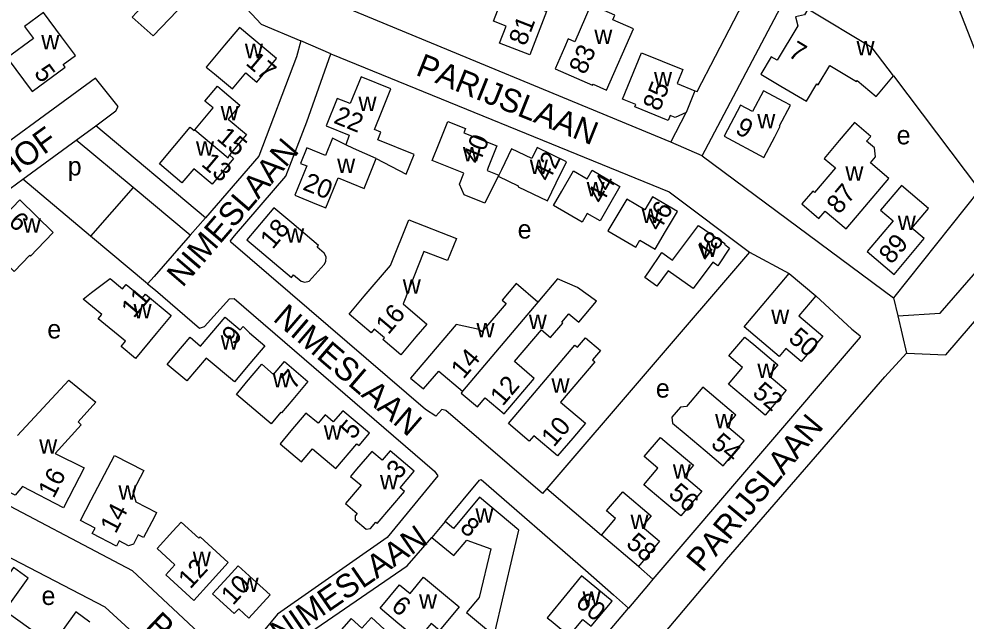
# Model space of a CAD drawing. Extents: x 157768 to 159790, y 387230 to 389604.
# Drawn here: x 158292.2 to 158494.9, y 388797.9 to 388926.9 of the extents above; entities that cross this region are included whole.
import ezdxf

# ---------------------------------------------------------------- set-up
doc = ezdxf.new("R2010")
doc.units = 0
for name, color, linetype in [('BLT_Basislijn', 7, 'Continuous'), ('BLT_Bebouwing', 7, 'Continuous'), ('BLT_Centroide', 7, 'Continuous'), ('BLT_Huisnummer', 7, 'Continuous'), ('BLT_Onderverdeling_panden', 7, 'Continuous'), ('BLT_Straatnaam', 7, 'Continuous')]:
    doc.layers.add(name, color=color, linetype=linetype)

msp = doc.modelspace()

# ---------------------------------------------------------------- linework, layer by layer
at = {"layer": 'BLT_Basislijn'}
for p, q in [((158431.74, 388900.51), (158362.74, 388929.08)), ((158358.97, 388919.46), (158352.55, 388922.18)), ((158304.47, 388900.97), (158308.62, 388904.02)), ((158332.14, 388884.34), (158308.62, 388904.02)), ((158293.03, 388892.57), (158304.47, 388900.97)), ((158316.62, 388890.8), (158304.47, 388900.97)), ((158438.43, 388897.56), (158431.74, 388900.51)), ((158255.34, 388864.91), (158293.03, 388892.57)), ((158307.51, 388880.4), (158293.03, 388892.57)), ((158316.62, 388890.8), (158307.51, 388880.4)), ((158328.86, 388880.57), (158316.62, 388890.8)), ((158332.14, 388884.34), (158328.86, 388880.57)), ((158319.7, 388870.15), (158307.51, 388880.4)), ((158448.59, 388876.93), (158405.18, 388826.37)), ((158448.59, 388876.93), (158457.1, 388872.4)), ((158480.33, 388863.3), (158482.23, 388855.29)), ((158383.44, 388819.3), (158390.75, 388828.15)), ((158390.75, 388828.15), (158391.16, 388828.23)), ((158391.16, 388828.23), (158413.5, 388808.81)), ((158405.18, 388826.37), (158416.89, 388816.34)), ((158375.33, 388809.8), (158380.57, 388815.86)), ((158352.11, 388793.82), (158375.33, 388809.8)), ((158427.9, 388806.93), (158424.82, 388809.65)), ((158413.5, 388808.81), (158419.44, 388803.53)), ((158419.44, 388803.53), (158422.65, 388800.7)), ((158416.4, 388793.31), (158422.65, 388800.7))]:
    msp.add_line(p, q, dxfattribs=at)
for points in [[(158217.7, 388922.2), (158241.39, 388936.76), (158256.85, 388946.34), (158278.36, 388958.55), (158301, 388970.67), (158302.4, 388970.48), (158344.06, 388925.81), (158352.55, 388922.18)], [(158505.09, 388881.94), (158513.06, 388891.11), (158498.54, 388915.97), (158492.75, 388930.78), (158491.71, 388938.14)], [(158436.91, 388911.53), (158437.35, 388911.35), (158449.16, 388934.14)], [(158438.43, 388897.56), (158456.57, 388931.96)], [(158352.55, 388922.18), (158351.59, 388918.78), (158343.57, 388897.49), (158332.14, 388884.34)], [(158405.18, 388826.37), (158404.25, 388825.3), (158383.56, 388843.02), (158382.69, 388843.23), (158381.47, 388841.81), (158379.24, 388843.24), (158337.52, 388879.07), (158337.46, 388879.39), (158338.33, 388880.47), (158349.31, 388893.24), (158353.79, 388904.84), (158358.97, 388919.46)], [(158358.97, 388919.46), (158431.36, 388889.84), (158448.59, 388876.93)], [(158308.62, 388904.02), (158312.94, 388907.19), (158313.42, 388908.14), (158308.58, 388914.19), (158250.43, 388871.67)], [(158479.43, 388914.71), (158497.83, 388890.31), (158479.42, 388867.16)], [(158431.74, 388900.51), (158435.02, 388906.85)], [(158438.43, 388897.56), (158479.42, 388867.16)], [(158482.23, 388855.29), (158490.58, 388854.93), (158513.94, 388882.12), (158517.63, 388885.18), (158521.9, 388885.49), (158565.66, 388865.34), (158569.12, 388863.56), (158573.32, 388860.89)], [(158328.86, 388880.57), (158321.16, 388871.71), (158319.7, 388870.15)], [(158480.33, 388863.3), (158489.42, 388863.92), (158505.09, 388881.94)], [(158319.7, 388870.15), (158321.4, 388868.83), (158330.85, 388860.65), (158331.93, 388861), (158337.3, 388866.95), (158338.24, 388867.06), (158381.15, 388830.03), (158381.88, 388829.07), (158371.05, 388815.86), (158347.55, 388799.4), (158338.32, 388788.26)], [(158462.77, 388867.62), (158470.5, 388860.47), (158472.2, 388859.12), (158472.25, 388858.78), (158427.9, 388806.93)], [(158479.42, 388867.16), (158480.33, 388863.3)], [(158255.34, 388864.91), (158283.64, 388826.08), (158316.42, 388808.74), (158338.32, 388788.26)], [(158435.57, 388745.97), (158422.92, 388761.25), (158425, 388788.91), (158431.41, 388796.6), (158443.67, 388811.14), (158477.57, 388850.28), (158482.23, 388855.29)], [(158345.09, 388769.27), (158310.62, 388800.89), (158285.46, 388813.98), (158277.79, 388808.18)], [(158427.9, 388806.93), (158426.93, 388805.79), (158422.65, 388800.7)]]:
    msp.add_lwpolyline(points, dxfattribs=at)
at = {"layer": 'BLT_Bebouwing'}
for p, q in [((158457.1, 388872.4), (158462.77, 388867.62)), ((158424.82, 388809.65), (158416.89, 388816.34))]:
    msp.add_line(p, q, dxfattribs=at)
for points in [[(158325.04, 388930.87), (158328.72, 388934.25), (158322.66, 388940.88), (158319.8, 388938.27), (158318.62, 388939.56), (158318.96, 388939.86), (158315.64, 388943.49), (158311.96, 388940.11), (158310.44, 388938.72), (158314.96, 388933.78), (158314.52, 388933.38), (158318.3, 388929.25), (158316.42, 388927.26), (158320.96, 388923.28), (158326.06, 388928.65), (158324.3, 388930.2), (158325.04, 388930.87)], [(158403.34, 388923.89), (158401.53, 388919.23), (158395.1, 388921.73), (158396.51, 388925.38), (158393.79, 388926.42), (158396.17, 388932.56), (158397.31, 388935.48), (158402.89, 388933.31), (158401.57, 388929.91), (158405.14, 388928.52), (158403.34, 388923.89)], [(158415.16, 388929.68), (158414.63, 388929.91), (158411.18, 388921.99), (158409.77, 388922.61), (158408.97, 388920.78), (158406.97, 388916.2), (158415, 388912.7), (158415.09, 388912.9), (158418, 388911.63), (158423.74, 388924.79), (158419.32, 388926.72), (158419.74, 388927.68), (158415.16, 388929.68)], [(158301.3, 388923.07), (158297.44, 388928.29), (158293.4, 388925.3), (158295.32, 388922.71), (158289.69, 388918.55), (158295.02, 388911.34), (158302.06, 388916.54), (158301.64, 388917.11), (158304.27, 388919.05), (158301.3, 388923.07)], [(158461.07, 388928.97), (158460.36, 388927.8), (158458.42, 388927.34), (158458.94, 388925.45), (158454.49, 388918.05), (158453.25, 388918.79), (158451.04, 388915.11), (158455.32, 388912.53), (158460.76, 388909.26), (158463, 388912.98), (158463.31, 388912.8), (158465.81, 388916.96), (158471.5, 388913.53), (158471.64, 388913.7), (158475.72, 388910.27), (158476.23, 388910.88), (158479.43, 388914.71)], [(158479.43, 388914.71), (158474.87, 388920.68), (158461.07, 388928.97)], [(158336.17, 388921.26), (158332.3, 388916.6), (158334.05, 388915.14), (158337.88, 388911.93), (158340.75, 388915.35), (158343.11, 388913.36), (158347.35, 388918.4), (158339.39, 388925.09), (158336.17, 388921.26)], [(158435.02, 388906.85), (158432.66, 388905.81), (158431.61, 388906.23), (158431.19, 388905.18), (158424.01, 388908.08), (158424.23, 388908.61), (158421.43, 388909.74), (158425.43, 388919.66)], [(158425.43, 388919.66), (158434.28, 388916.09), (158433.07, 388913.07), (158436.91, 388911.53)], [(158369.93, 388907.31), (158371.81, 388911.94), (158365.44, 388914.52), (158363.1, 388908.76), (158360.32, 388909.89), (158357.93, 388903.99), (158362.9, 388901.98), (158362.17, 388899.97)], [(158329.82, 388903.14), (158333.76, 388907.84), (158332, 388909.32), (158334.68, 388912.51), (158335.68, 388911.67), (158339.51, 388908.45), (158336.98, 388905.44), (158340.91, 388902.13), (158337.24, 388897.77)], [(158436.91, 388911.53), (158435.02, 388906.85)], [(158456.01, 388909.14), (158451.59, 388911.48), (158449.24, 388907.05), (158446.67, 388908.41), (158443.14, 388901.77), (158451.65, 388897.26), (158453.99, 388901.68), (158455.18, 388903.92), (158455.01, 388904.01), (158457.35, 388908.43), (158456.01, 388909.14)], [(158368.65, 388896.99), (158375.11, 388893.65), (158376.82, 388897.86), (158369.02, 388901.02), (158369.69, 388902.66), (158368.28, 388903.23), (158369.93, 388907.31)], [(158394.8, 388893.22), (158391.9, 388887.45), (158387.53, 388889.2), (158386.5, 388891.53), (158387.45, 388893.89), (158380.68, 388896.61), (158382.16, 388900.31), (158384.02, 388904.95), (158387.81, 388903.43), (158387.45, 388902.54), (158394.51, 388899.71), (158392.65, 388895.07)], [(158337.24, 388897.77), (158338.14, 388897.01), (158333.54, 388891.53), (158329.62, 388894.83), (158327.09, 388891.83), (158322.28, 388895.89), (158328.84, 388903.69), (158329.68, 388902.98), (158329.82, 388903.14)], [(158472.51, 388885.74), (158478.42, 388892.74), (158474.48, 388896.06), (158475.57, 388897.36), (158475.36, 388899.27), (158473.65, 388900.71), (158474.54, 388901.76), (158471.04, 388904.71), (158467.79, 388900.86), (158464.57, 388897.04), (158466.97, 388895.01), (158462.51, 388889.72), (158462.14, 388890.03), (158459.81, 388887.27), (158463.45, 388884.19), (158464.75, 388885.74), (158469.28, 388881.92), (158472.51, 388885.74)], [(158362.17, 388899.97), (158359.34, 388901.38), (158357.85, 388897.69), (158353.8, 388899.33), (158352.44, 388895.97), (158353.82, 388895.41), (158351.27, 388889.14), (158355.91, 388887.26), (158357.91, 388886.44), (158360.52, 388892.86), (158366.06, 388890.61), (158368.65, 388896.99)], [(158407.23, 388891.83), (158409.42, 388896.32), (158403.15, 388899.38), (158401.98, 388896.99), (158397.67, 388899.09), (158395.47, 388894.6), (158394.91, 388893.45)], [(158392.65, 388895.07), (158392.4, 388894.46), (158394.91, 388893.45)], [(158394.8, 388893.22), (158399.04, 388891.16), (158399.05, 388890.97), (158405.32, 388887.92), (158407.23, 388891.83)], [(158418.36, 388886.69), (158416.59, 388883.63), (158413.83, 388885.23), (158412.75, 388883.37), (158406.62, 388886.92), (158408.41, 388890.02), (158410.92, 388894.34), (158413.82, 388892.66), (158414.88, 388894.48), (158420.86, 388891.01), (158418.36, 388886.69)], [(158481.11, 388891.2), (158476.66, 388885.93), (158479.32, 388883.68), (158473.75, 388877.09), (158479.53, 388872.19), (158486.01, 388879.85), (158483.36, 388882.09), (158486.91, 388886.29), (158481.11, 388891.2)], [(158430.59, 388881.36), (158433.15, 388885.65), (158427.83, 388888.83), (158426.15, 388886.01), (158422.32, 388888.29), (158419.75, 388884), (158418.29, 388881.55), (158424.22, 388878.01), (158425.14, 388879.55), (158428.36, 388877.62), (158430.59, 388881.36)], [(158296.06, 388877.57), (158299.55, 388881.15), (158292.39, 388888.13), (158287.49, 388883.11), (158289.87, 388880.79), (158286.52, 388877.35), (158290.1, 388873.86), (158291.15, 388872.83), (158294.51, 388876.28), (158294.66, 388876.13), (158296.06, 388877.57)], [(158357.51, 388876.77), (158356, 388878.05), (158356.29, 388878.38), (158350.58, 388883.21), (158346.77, 388886.44), (158340.95, 388879.57), (158350.51, 388871.55), (158350.99, 388872.12), (158352.58, 388870.77), (158353.41, 388870.52), (158354.31, 388870.76), (158357.54, 388874.34), (158357.9, 388874.98), (158357.93, 388875.92), (158357.51, 388876.77)], [(158377.19, 388858.81), (158373.96, 388854.99), (158370.12, 388858.24), (158370.43, 388858.61), (158368.27, 388860.44), (158367.62, 388859.67), (158362.88, 388863.69), (158366.11, 388867.5), (158371.72, 388874.13), (158375.69, 388883.91), (158385.85, 388879.85), (158383.96, 388875.16), (158378.89, 388877.1), (158374.44, 388865.86), (158379.52, 388861.55), (158377.19, 388858.81)], [(158441.79, 388874.04), (158440.72, 388874.83), (158436.55, 388869.18), (158431.14, 388872.92), (158428.74, 388869.67), (158426.2, 388871.55), (158427.03, 388872.77), (158429.85, 388876.89), (158432.13, 388875.21), (158437.64, 388882.67), (158443.29, 388878.8), (158443.2, 388878.67), (158444.32, 388877.84), (158441.79, 388874.04)], [(158462.77, 388867.62), (158459.13, 388863.3), (158464.27, 388858.97), (158459.68, 388853.52), (158456.37, 388856.31), (158454.94, 388854.62), (158447.44, 388860.94), (158457.1, 388872.4)], [(158321.6, 388859.55), (158317.16, 388854.2), (158314.05, 388856.78), (158314.97, 388857.88), (158309.16, 388862.7), (158309.92, 388863.62), (158305.94, 388866.92), (158307.73, 388868.28), (158311.71, 388871.3), (158314.37, 388869.1), (158315.15, 388870.05), (158318.64, 388867.15), (158319.31, 388867.95), (158324.79, 388863.4), (158321.59, 388859.56)], [(158387.17, 388847.16), (158386.85, 388846.78), (158390.37, 388843.8), (158392.01, 388845.74), (158396.06, 388842.31), (158399.29, 388846.13), (158402.51, 388849.93), (158398.27, 388853.51), (158404.06, 388860.35), (158406.02, 388858.68), (158408.62, 388861.75), (158408.38, 388861.96), (158409.92, 388863.78), (158412.05, 388861.98), (158415.83, 388866.45), (158411.73, 388869.37), (158407.51, 388871.24), (158403.3, 388866.27)], [(158403.3, 388866.27), (158398.64, 388870.21), (158395.66, 388866.7), (158396.51, 388865.98), (158391.32, 388859.86), (158390.69, 388860.4), (158385.76, 388861.49), (158376.03, 388850), (158378.8, 388847.66), (158382.05, 388851.5), (158387.17, 388847.16)], [(158341.6, 388853.08), (158338.31, 388849.17), (158332.24, 388854.28), (158328.1, 388849.37), (158323.91, 388852.91), (158325.59, 388854.91), (158328.82, 388858.73), (158331.09, 388856.82), (158336.33, 388863.03), (158339.55, 388860.31), (158340.22, 388861), (158341.54, 388859.66), (158344.82, 388856.9), (158341.6, 388853.08)], [(158410.74, 388837.13), (158407.51, 388833.32), (158402.43, 388837.62), (158401.43, 388836.44), (158396.96, 388840.23), (158400.19, 388844.05), (158411.19, 388857.04), (158411.76, 388856.57), (158413.48, 388858.6), (158416.68, 388855.9), (158414.95, 388853.86), (158415.45, 388853.44), (158408.16, 388844.82), (158413.45, 388840.34), (158410.74, 388837.13)], [(158449.48, 388857.2), (158454.68, 388852.82), (158452.74, 388850.52), (158456.47, 388847.38), (158451.96, 388842.04), (158448.14, 388845.26), (158444.07, 388848.69), (158447.1, 388852.27), (158444.19, 388854.73), (158447.61, 388858.78), (158449.48, 388857.2)], [(158350.83, 388845.43), (158348.38, 388842.53), (158348.23, 388842.65), (158346.17, 388840.22), (158338.73, 388846.5), (158340.94, 388849.11), (158344.16, 388852.93), (158346.72, 388850.77), (158349.02, 388853.5), (158354.05, 388849.25), (158350.83, 388845.43)], [(158291.87, 388837.7), (158302.84, 388849.57), (158308.65, 388844.8), (158304.85, 388840.58), (158305.49, 388840), (158299.96, 388833.82), (158306.13, 388830.74), (158304.01, 388826.65), (158301.71, 388822.21), (158292.98, 388826.74), (158291.36, 388824.94), (158288.43, 388826.43), (158284.37, 388830.07)], [(158440.43, 388846.45), (158438.56, 388848.03), (158435.08, 388843.9), (158433.8, 388843.77), (158431.99, 388841.61), (158432.1, 388840.35), (158435.01, 388837.89), (158439.1, 388834.44), (158442.92, 388831.22), (158447.44, 388836.58), (158443.67, 388839.75), (158445.63, 388842.07), (158440.43, 388846.45)], [(158365, 388835.53), (158367.23, 388838.18), (158361.51, 388843), (158359.49, 388840.61), (158357.73, 388842.09), (158356.23, 388840.3), (158353.63, 388842.5), (158350.41, 388838.68), (158348.1, 388835.93), (158352.66, 388832.08), (158355, 388834.85), (158360.03, 388830.6), (158364.52, 388835.93), (158365, 388835.53)], [(158431.39, 388835.68), (158436.59, 388831.3), (158434.61, 388828.95), (158438.36, 388825.79), (158433.86, 388820.45), (158430.04, 388823.67), (158425.97, 388827.1), (158428.99, 388830.68), (158426.05, 388833.17), (158429.5, 388837.27), (158431.39, 388835.68)], [(158364.49, 388830.47), (158363.19, 388828.93), (158365.45, 388827.02), (158362.13, 388823.09), (158364.6, 388821.01), (158364.15, 388820.47), (158364.2, 388819.6), (158366.54, 388817.63), (158367.43, 388817.76), (158368.58, 388819.11), (158368.91, 388818.83), (158374.72, 388825.72), (158373.81, 388826.49), (158376.83, 388830.07), (158371.68, 388834.41), (158369.97, 388832.38), (158367.71, 388834.29), (158364.49, 388830.47)], [(158321.2, 388820.26), (158318.87, 388815.83), (158317.75, 388816.42), (158316.71, 388814.43), (158315.63, 388814.05), (158313.64, 388815.1), (158313.05, 388813.97), (158307.89, 388816.68), (158308.49, 388817.81), (158305.34, 388819.47), (158307.67, 388823.89), (158312.68, 388833.43), (158318.92, 388830.16), (158316.57, 388825.68), (158317.25, 388823.48), (158321.67, 388821.16), (158321.2, 388820.26)], [(158398.09, 388812.57), (158399.23, 388817.43), (158390.79, 388824.47), (158385.23, 388817.8), (158383.44, 388819.3)], [(158416.89, 388816.34), (158419.9, 388819.9), (158417.98, 388821.52), (158421.45, 388825.64), (158427.53, 388820.51), (158425.58, 388818.19), (158429.34, 388815.02), (158424.82, 388809.65)], [(158332.98, 388806.06), (158337.01, 388810.48), (158331, 388815.97), (158330.73, 388815.67), (158326.94, 388819.11), (158325.17, 388817.18), (158321.8, 388813.48), (158325.59, 388810.02), (158323.61, 388807.84), (158329.61, 388802.36), (158332.98, 388806.06)], [(158383.44, 388819.3), (158380.57, 388815.86)], [(158380.57, 388815.86), (158385.27, 388811.95), (158388.06, 388815.29), (158393.22, 388813.41), (158390.72, 388803.01), (158388.03, 388799.78), (158391.87, 388796.58), (158393.91, 388794.88), (158398.09, 388812.57)], [(158342.27, 388806.92), (158345.96, 388803.55), (158341.44, 388798.59), (158339.24, 388800.59), (158338.27, 388799.53), (158333.64, 388803.76), (158337.01, 388807.45), (158339.13, 388809.78), (158342.27, 388806.92)], [(158294.24, 388796.5), (158289.18, 388800.13), (158294.19, 388807.13), (158291.05, 388809.39), (158290.18, 388808.17)], [(158409.45, 388803.8), (158405.3, 388798.64), (158406.11, 388797.97), (158409.95, 388794.77), (158412.89, 388798.3), (158414.66, 388796.82), (158419.16, 388802.21), (158412.65, 388807.64), (158409.45, 388803.8)], [(158382.65, 388804.11), (158386.41, 388800.99), (158382.21, 388795.94), (158380.44, 388797.42), (158377.56, 388793.96), (158373.33, 388797.48), (158369.49, 388800.68), (158373.69, 388805.72), (158375.92, 388803.85), (158378.81, 388807.32), (158382.65, 388804.11)], [(158307.4, 388797.71), (158304.34, 388799.91), (158299.31, 388792.88), (158294.24, 388796.5)], [(158365.66, 388786.78), (158368.43, 388789.85), (158371.58, 388787.02), (158374.98, 388790.8), (158375.62, 388791.51), (158371.34, 388795.36), (158367.65, 388798.68), (158365.61, 388796.41), (158363.34, 388798.46), (158358.57, 388793.16), (158362.29, 388789.82)]]:
    msp.add_lwpolyline(points, dxfattribs=at)
at = {"layer": 'BLT_Onderverdeling_panden'}
for p, q in [((158394.91, 388893.45), (158394.8, 388893.22)), ((158403.3, 388866.27), (158387.17, 388847.16))]:
    msp.add_line(p, q, dxfattribs=at)
for points in [[(158329.82, 388903.14), (158336.96, 388897.17), (158337.24, 388897.77)], [(158363.82, 388899.16), (158362.17, 388899.97)], [(158368.65, 388896.99), (158363.82, 388899.16)]]:
    msp.add_lwpolyline(points, dxfattribs=at)

# ---------------------------------------------------------------- texts
at = {"layer": 'BLT_Centroide'}
for s, p in [('w', (158296.98, 388920.36)), ('w', (158415.36, 388921.56)), ('w', (158340.56, 388918.5)), ('w', (158471.5, 388919.12)), ('w', (158428.14, 388912.48)), ('w', (158364.88, 388907.16)), ('w', (158335.36, 388905.22)), ('w', (158450.25, 388903.47)), ('e', (158480.09, 388900.04)), ('w', (158330.09, 388897.62)), ('w', (158387.23, 388896.38)), ('w', (158360.31, 388893.91)), ('w', (158401.56, 388893.66)), ('p', (158302.64, 388893.38)), ('w', (158469.11, 388892.25)), ('w', (158413.72, 388888.94)), ('w', (158425.49, 388883.22)), ('w', (158480.33, 388881.7)), ('w', (158293.03, 388881.12)), ('e', (158398.96, 388879.87)), ('w', (158349.39, 388879)), ('w', (158437.85, 388875.94)), ('w', (158374.36, 388868.06)), ('w', (158316.73, 388862.75)), ('w', (158453.23, 388861.58)), ('w', (158401.34, 388860.53)), ('e', (158298.27, 388858.48)), ('w', (158390.14, 388858.69)), ('w', (158335.37, 388856.09)), ('w', (158450.27, 388850)), ('w', (158346.5, 388848)), ('w', (158406.2, 388846.83)), ('e', (158428.54, 388845.8)), ('w', (158441.22, 388839.22)), ('w', (158357.45, 388836.81)), ('w', (158296.52, 388833.81)), ('w', (158432.17, 388828.45)), ('w', (158369.48, 388826.16)), ('w', (158313.5, 388823.92)), ('w', (158389.91, 388819.02)), ('w', (158423.11, 388817.66)), ('w', (158329.41, 388809.7)), ('w', (158339.65, 388804.19)), ('e', (158297.03, 388801.39)), ('w', (158377.84, 388800.62)), ('w', (158412.84, 388801.22))]:
    msp.add_text(s, height=4, dxfattribs=at).set_placement(p)
at = {"layer": 'BLT_Huisnummer'}
for s, rotation, p in [('81', 68.7667, (158400.63, 388920.95)), ('83', 66.4222, (158413.43, 388914.8)), ('7', 328.9929, (158456.64, 388919)), ('17', 319.9382, (158340.55, 388917.2)), ('5', 306.4587, (158295.27, 388915.33)), ('85', 68.0404, (158429.3, 388906.95)), ('22', 337.9358, (158359.35, 388904.7)), ('9', 332.0749, (158445.31, 388902.53)), ('15', 319.9382, (158334.33, 388901.09)), ('40', 68.1198, (158390.74, 388895.61)), ('13', 319.9382, (158331.02, 388895.59)), ('42', 63.9833, (158405.7, 388891.85)), ('20', 337.939, (158352.74, 388890.42)), ('44', 59.9267, (158417.05, 388887.08)), ('87', 49.8424, (158467.76, 388884.89)), ('46', 59.1448, (158429.3, 388881.21)), ('6', 315.7131, (158289.74, 388883.18)), ('18', 49.7529, (158346.52, 388877.41)), ('48', 53.5673, (158439.75, 388874.71)), ('89', 49.7868, (158478.96, 388874.18)), ('11', 49.8712, (158316.78, 388862.65)), ('16', 49.7455, (158371.27, 388859.11)), ('9', 49.8712, (158338.33, 388856.83)), ('50', 319.876, (158456.69, 388858.13)), ('14', 49.8364, (158387.35, 388849.6)), ('7', 49.8712, (158351.07, 388847.37)), ('12', 49.7529, (158395.75, 388843.81)), ('52', 319.876, (158449, 388846.47)), ('5', 49.8712, (158363.73, 388836.65)), ('10', 49.7367, (158406.7, 388835.03)), ('54', 319.876, (158440.1, 388835.56)), ('3', 49.8712, (158373.54, 388828.11)), ('16', 62.6561, (158299.62, 388824.07)), ('56', 319.876, (158431.02, 388824.83)), ('14', 62.2767, (158312.89, 388816.49)), ('8', 320.1964, (158386.36, 388817.55)), ('58', 319.876, (158421.95, 388814.18)), ('12', 47.6275, (158328.87, 388804.65)), ('10', 47.6275, (158338.02, 388801.16)), ('60', 320.2003, (158411.09, 388801.47)), ('6', 320.193, (158371.66, 388800.66))]:
    msp.add_text(s, height=4, rotation=rotation, dxfattribs=at).set_placement(p)
at = {"layer": 'BLT_Straatnaam'}
for s, rotation, p in [('PARIJSLAAN', 338.2073, (158376.9, 388914.98)), ('FREJUSHOF', 35.7592, (158268.24, 388876.64)), ('NIMESLAAN', 49.326, (158327.22, 388869.24)), ('NIMESLAAN', 319.3293, (158346.36, 388862.43)), ('PARIJSLAAN', 50.1633, (158438.5, 388808.16)), ('NIMESLAAN', 34.5154, (158348.25, 388792.78)), ('PARIJSLAAN', 316.3568, (158319.12, 388796.72))]:
    msp.add_text(s, height=5, rotation=rotation, dxfattribs=at).set_placement(p)

doc.saveas('drawing.dxf')
